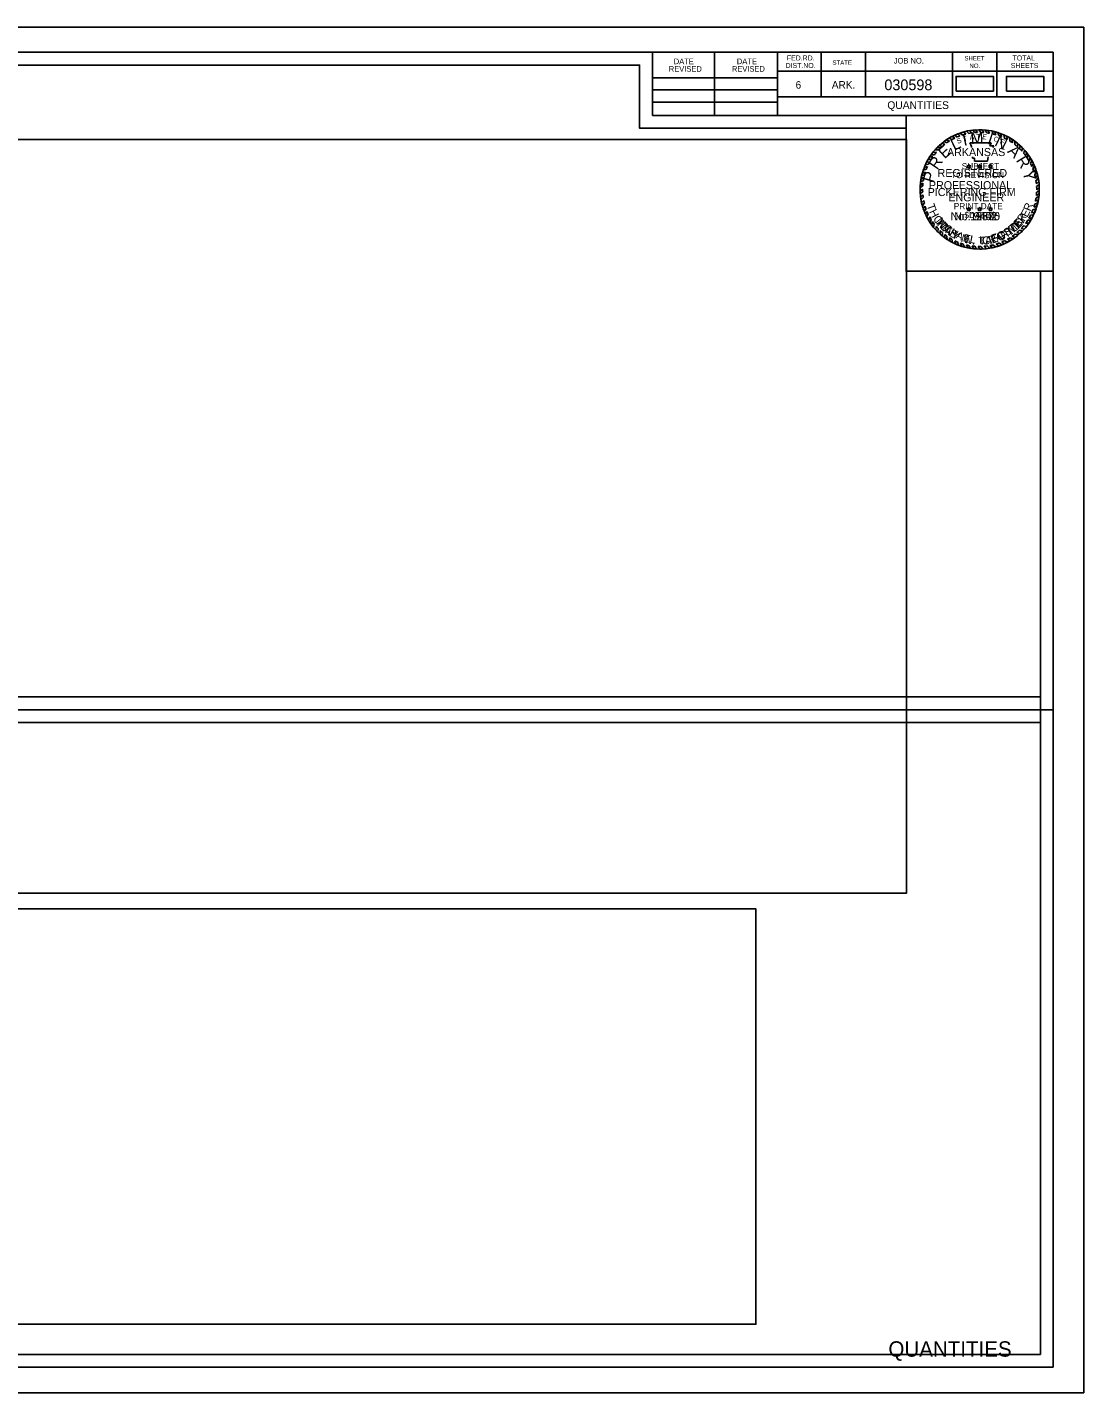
# Model space of a CAD drawing. Extents: x 1369904 to 1372237, y 380119 to 380332.
# Drawn here: x 1370071.9 to 1370236.9, y 380119.1 to 380332.4 of the extents above; entities that cross this region are included whole.
import ezdxf

# ---------------------------------------------------------------- set-up
doc = ezdxf.new("R2010")
doc.units = 0
for name, color, linetype in [('Default', 7, 'Continuous'), ('R_Border', 7, 'Continuous'), ('R_Border Notes', 7, 'Continuous'), ('R_Border Plan-Plan', 7, 'Continuous'), ('R_Border Title', 7, 'Continuous'), ('R_No Plot', 7, 'Continuous'), ('STAMP_PE_CRAFTON', 7, 'Continuous'), ('STAMP_PE_FOSTER', 7, 'Continuous'), ('STAMP_PE_SEAL-INFO', 7, 'Continuous'), ('STAMP_PE_TAEGTMEYER', 7, 'Continuous'), ('STAMP_PE_TXT', 7, 'Continuous'), ('STAMP_PRELIMINARY', 7, 'Continuous')]:
    doc.layers.add(name, color=color, linetype=linetype)

msp = doc.modelspace()

# ---------------------------------------------------------------- linework, layer by layer
at = {"layer": 'Default'}
for points in [[(1370217, 380322.41), (1370222.83, 380322.41), (1370222.83, 380324.72), (1370217, 380324.72)], [(1370224.87, 380322.41), (1370230.7, 380322.41), (1370230.7, 380324.72), (1370224.87, 380324.72)], [(1369918.18, 380197.09), (1370209.24, 380197.09), (1370209.24, 380314.85), (1369918.18, 380314.85)], [(1369962.47, 380129.75), (1370185.72, 380129.75), (1370185.72, 380194.65), (1369962.47, 380194.65)]]:
    msp.add_lwpolyline(points, close=True, dxfattribs=at)
at = {"layer": 'R_Border'}
for p, q in [((1369916, 380328.5), (1370232.18, 380328.5)), ((1370169.54, 380318.62), (1370169.54, 380328.5)), ((1370179.22, 380318.62), (1370179.22, 380328.5)), ((1370189.08, 380328.5), (1370189.08, 380318.62)), ((1370195.92, 380328.5), (1370195.92, 380321.56)), ((1370202.86, 380328.5), (1370202.86, 380321.56)), ((1370216.44, 380328.5), (1370216.44, 380321.56)), ((1370223.38, 380328.5), (1370223.38, 380321.56)), ((1370232.18, 380123.04), (1370232.18, 380328.5)), ((1370232.18, 380325.56), (1370189.08, 380325.56)), ((1370232.18, 380325.58), (1370232.18, 380325.58)), ((1370169.54, 380324.48), (1370189.08, 380324.48)), ((1370169.54, 380322.62), (1370189.08, 380322.62)), ((1370232.18, 380321.56), (1370189.08, 380321.56)), ((1370192.04, 380321.56), (1370232.18, 380321.56)), ((1370169.54, 380320.68), (1370189.08, 380320.68)), ((1370232.18, 380318.62), (1370169.54, 380318.62)), ((1370232.18, 380123.04), (1369916, 380123.04))]:
    msp.add_line(p, q, dxfattribs=at)
at = {"layer": 'R_Border Plan-Plan'}
msp.add_line((1369916, 380225.77), (1370232.18, 380225.77), dxfattribs=at)
at = {"layer": 'R_No Plot'}
for points in [[(1369903.6, 380332.4), (1370236.94, 380332.4), (1370236.94, 380119.06), (1369903.6, 380119.06)], [(1370230.18, 380227.77), (1369918, 380227.77), (1369918, 380326.5), (1370167.54, 380326.5), (1370167.54, 380316.62), (1370185.08, 380316.62), (1370209.18, 380316.62), (1370209.18, 380294.29), (1370230.18, 380294.29)], [(1369918, 380326.5), (1370167.54, 380326.5), (1370167.54, 380316.62), (1370185.08, 380316.62), (1370209.18, 380316.62), (1370209.18, 380294.29), (1370230.18, 380294.29), (1370230.18, 380125.04), (1369918, 380125.04)], [(1370209.18, 380318.62), (1370232.18, 380318.62), (1370232.18, 380294.29), (1370209.18, 380294.29)], [(1369918, 380223.77), (1370230.18, 380223.77), (1370230.18, 380125.04), (1369918, 380125.04)]]:
    msp.add_lwpolyline(points, close=True, dxfattribs=at)
at = {"layer": 'STAMP_PE_SEAL-INFO'}
for p, q in [((1370215.52, 380314.83), (1370215.96, 380314.63)), ((1370215.91, 380315.07), (1370216.34, 380314.85)), ((1370216.36, 380315.33), (1370216.82, 380315.1)), ((1370216.79, 380315.54), (1370217.18, 380315.26)), ((1370217.29, 380315.75), (1370217.59, 380315.43)), ((1370217.64, 380315.88), (1370218.02, 380315.57)), ((1370218.23, 380316.06), (1370218.52, 380315.71)), ((1370218.62, 380316.16), (1370218.98, 380315.82)), ((1370219.1, 380316.26), (1370219.4, 380315.89)), ((1370219.62, 380316.33), (1370219.9, 380315.95)), ((1370220.35, 380315.97), (1370220.04, 380316.37)), ((1370220.85, 380315.98), (1370220.57, 380316.39)), ((1370221.31, 380315.96), (1370221.05, 380316.38)), ((1370221.82, 380315.91), (1370221.52, 380316.35)), ((1370222.24, 380315.84), (1370221.98, 380316.3)), ((1370222.8, 380315.72), (1370222.63, 380316.18)), ((1370223.21, 380315.62), (1370223.05, 380316.09)), ((1370223.66, 380315.47), (1370223.52, 380315.95)), ((1370224.08, 380315.31), (1370223.93, 380315.81)), ((1370224.54, 380315.1), (1370224.43, 380315.6)), ((1370224.98, 380314.87), (1370224.9, 380315.38)), ((1370225.37, 380314.65), (1370225.33, 380315.15)), ((1370225.81, 380314.36), (1370225.77, 380314.88)), ((1370213.38, 380312.86), (1370213.93, 380312.88)), ((1370213.72, 380313.27), (1370214.24, 380313.23)), ((1370214.04, 380313.61), (1370214.59, 380313.57)), ((1370214.38, 380313.94), (1370214.84, 380313.8)), ((1370214.72, 380314.24), (1370215.25, 380314.14)), ((1370215.1, 380314.56), (1370215.56, 380314.36)), ((1370219.16, 380314.36), (1370222.5, 380314.36)), ((1370219.28, 380314.05), (1370219.16, 380314.36)), ((1370219.38, 380313.75), (1370219.28, 380314.05)), ((1370219.39, 380313.64), (1370219.38, 380313.75)), ((1370222.5, 380314.36), (1370222.28, 380313.87)), ((1370222.28, 380313.87), (1370222.91, 380313.87)), ((1370222.91, 380313.87), (1370222.76, 380313.64)), ((1370226.17, 380314.1), (1370226.2, 380314.58)), ((1370226.61, 380313.72), (1370226.63, 380314.25)), ((1370226.92, 380313.43), (1370226.99, 380313.93)), ((1370227.28, 380313.06), (1370227.35, 380313.58)), ((1370227.56, 380312.74), (1370227.69, 380313.21)), ((1370227.88, 380312.32), (1370228.02, 380312.82)), ((1370212.01, 380310.5), (1370212.52, 380310.64)), ((1370212.2, 380310.93), (1370212.7, 380311.03)), ((1370212.39, 380311.32), (1370212.88, 380311.38)), ((1370212.62, 380311.74), (1370213.11, 380311.76)), ((1370212.86, 380312.14), (1370213.38, 380312.18)), ((1370213.1, 380312.49), (1370213.6, 380312.48)), ((1370219.58, 380311.93), (1370219.55, 380312.15)), ((1370219.89, 380311.93), (1370219.58, 380311.93)), ((1370219.89, 380311.5), (1370219.89, 380311.93)), ((1370221.92, 380311.5), (1370219.89, 380311.5)), ((1370221.94, 380311.84), (1370221.92, 380311.5)), ((1370222.02, 380312.15), (1370221.94, 380311.84)), ((1370228.1, 380312.01), (1370228.28, 380312.47)), ((1370228.41, 380311.51), (1370228.59, 380312)), ((1370228.61, 380311.14), (1370228.84, 380311.59)), ((1370228.84, 380310.66), (1370229.07, 380311.15)), ((1370228.98, 380310.32), (1370229.24, 380310.76)), ((1370211.88, 380308.48), (1370211.44, 380308.25)), ((1370211.97, 380308.94), (1370211.5, 380308.69)), ((1370211.6, 380309.18), (1370212.07, 380309.37)), ((1370211.71, 380309.59), (1370212.19, 380309.76)), ((1370211.86, 380310.09), (1370212.35, 380310.23)), ((1370229.18, 380309.77), (1370229.45, 380310.25)), ((1370229.28, 380309.41), (1370229.58, 380309.86)), ((1370229.42, 380308.85), (1370229.73, 380309.3)), ((1370229.49, 380308.47), (1370229.84, 380308.82)), ((1370211.79, 380307.62), (1370211.36, 380307.36)), ((1370211.77, 380307.12), (1370211.36, 380306.79)), ((1370211.78, 380306.72), (1370211.38, 380306.39)), ((1370211.82, 380308.04), (1370211.39, 380307.76)), ((1370229.55, 380307.96), (1370229.92, 380308.3)), ((1370229.55, 380306.11), (1370229.98, 380306.37)), ((1370229.58, 380307.54), (1370229.97, 380307.84)), ((1370229.59, 380306.62), (1370230, 380306.9)), ((1370229.6, 380307.03), (1370230, 380307.35)), ((1370211.81, 380306.22), (1370211.44, 380305.86)), ((1370211.86, 380305.79), (1370211.51, 380305.42)), ((1370211.94, 380305.33), (1370211.6, 380304.96)), ((1370212.03, 380304.91), (1370211.72, 380304.5)), ((1370212.16, 380304.47), (1370211.86, 380304.05)), ((1370229.15, 380304.28), (1370229.64, 380304.48)), ((1370229.3, 380304.77), (1370229.77, 380304.98)), ((1370229.4, 380305.23), (1370229.86, 380305.42)), ((1370229.49, 380305.73), (1370229.94, 380305.95)), ((1370212.3, 380304.04), (1370212.02, 380303.63)), ((1370212.46, 380303.62), (1370212.2, 380303.19)), ((1370212.64, 380303.23), (1370212.41, 380302.77)), ((1370212.87, 380302.77), (1370212.68, 380302.28)), ((1370213.11, 380302.37), (1370212.92, 380301.9)), ((1370213.31, 380302.06), (1370213.2, 380301.51)), ((1370228.2, 380302.27), (1370228.67, 380302.26)), ((1370228.37, 380302.55), (1370228.87, 380302.61)), ((1370228.64, 380303.05), (1370229.13, 380303.12)), ((1370228.8, 380303.39), (1370229.29, 380303.48)), ((1370229.01, 380303.9), (1370229.5, 380304.03)), ((1370213.59, 380301.67), (1370213.49, 380301.14)), ((1370213.89, 380301.29), (1370213.81, 380300.77)), ((1370214.2, 380300.95), (1370214.13, 380300.43)), ((1370214.52, 380300.63), (1370214.49, 380300.1)), ((1370214.86, 380300.32), (1370214.86, 380299.79)), ((1370215.22, 380300.02), (1370215.24, 380299.5)), ((1370226.23, 380300.09), (1370226.7, 380299.95)), ((1370226.5, 380300.32), (1370226.98, 380300.19)), ((1370226.91, 380300.69), (1370227.35, 380300.55)), ((1370227.16, 380300.95), (1370227.64, 380300.86)), ((1370227.55, 380301.38), (1370228.01, 380301.3)), ((1370227.86, 380301.78), (1370228.36, 380301.78)), ((1370215.56, 380299.77), (1370215.6, 380299.25)), ((1370215.99, 380299.49), (1370216.05, 380298.98)), ((1370216.34, 380299.28), (1370216.43, 380298.77)), ((1370216.82, 380299.03), (1370216.98, 380298.51)), ((1370217.19, 380298.87), (1370217.37, 380298.35)), ((1370217.69, 380298.67), (1370217.89, 380298.17)), ((1370218.09, 380298.54), (1370218.32, 380298.05)), ((1370218.6, 380298.4), (1370218.82, 380297.93)), ((1370219, 380298.31), (1370219.25, 380297.86)), ((1370219.5, 380298.23), (1370219.74, 380297.79)), ((1370219.94, 380298.19), (1370220.21, 380297.76)), ((1370220.42, 380298.16), (1370220.72, 380297.74)), ((1370220.88, 380298.16), (1370221.23, 380297.76)), ((1370221.4, 380298.18), (1370221.73, 380297.8)), ((1370221.84, 380298.23), (1370222.21, 380297.87)), ((1370222.28, 380298.3), (1370222.67, 380297.96)), ((1370222.78, 380298.4), (1370223.15, 380298.08)), ((1370223.24, 380298.53), (1370223.65, 380298.23)), ((1370223.73, 380298.69), (1370224.17, 380298.42)), ((1370224.15, 380298.85), (1370224.57, 380298.59)), ((1370224.61, 380299.06), (1370225.09, 380298.85)), ((1370225.01, 380299.28), (1370225.43, 380299.04)), ((1370225.43, 380299.52), (1370225.88, 380299.33)), ((1370225.77, 380299.75), (1370226.21, 380299.56))]:
    msp.add_line(p, q, dxfattribs=at)
for radius, start, end in [(9.32, 123.6199, 126.5906), (9.32, 117.6544, 120.8099), (8.91, 115.6869, 119.1583), (9.32, 111.3124, 114.7026), (8.91, 110.3086, 113.1659), (9.32, 105.2339, 109.0352), (8.91, 104.0352, 107.3615), (9.32, 99.7525, 102.7765), (8.91, 98.258, 101.0329), (9.32, 93.9381, 96.5517), (8.91, 92.1102, 95.0367), (9.32, 87.7298, 90.6707), (8.91, 85.9628, 88.9097), (9.32, 81.9732, 84.8236), (8.91, 79.9264, 82.696), (9.32, 75.3125, 77.9426), (8.91, 73.5575, 76.2314), (9.32, 69.6061, 72.3058), (8.91, 67.6248, 70.504), (9.32, 63.1329, 66.2704), (8.91, 61.1558, 64.3784), (9.32, 56.9003, 60.0942), (9.32, 141.6056, 144.4486), (8.91, 139.301, 142.5873), (9.32, 135.4021, 138.3031), (8.91, 133.1331, 136.2562), (9.32, 129.7326, 132.5376), (8.91, 127.5297, 130.9683), (8.91, 121.9746, 125.11), (8.91, 54.9238, 58.2702), (8.91, 48.3016, 52.0395), (9.32, 50.3492, 53.7159), (8.91, 42.2212, 45.5512), (9.32, 44.3405, 47.3929), (8.91, 36.135, 39.5311), (9.32, 38.1247, 41.2316), (9.32, 152.864, 155.5189), (8.91, 156.3402, 159.2319), (9.32, 147.0072, 149.899), (8.91, 151.0315, 153.573), (8.91, 145.0197, 148.2104), (8.91, 29.9032, 33.6645), (9.32, 31.9614, 35.4294), (8.91, 23.7732, 27.2211), (9.32, 25.9391, 29.0125), (9.32, 19.9538, 23.3141), (9.32, 170.0003, 172.6878), (9.32, 164.3068, 166.894), (9.32, 158.4077, 161.0701), (8.91, 167.9048, 170.9039), (8.91, 162.4331, 165.0013), (8.91, 17.6802, 21.4251), (8.91, 11.5444, 15.2364), (8.91, 5.7599, 9.0606), (9.32, 13.8421, 17.4447), (9.32, 7.5852, 10.8621), (9.32, 175.7409, 178.2066), (9.32, 181.7251, 184.1626), (8.91, 179.6454, 182.2633), (8.91, 173.73, 176.4734), (8.91, 353.8632, 357.1274), (8.91, 359.7329, 3.0639), (9.32, 1.7215, 4.7268), (9.32, 355.7156, 358.9569), (9.32, 187.4204, 190.1927), (9.32, 193.0369, 195.9973), (8.91, 185.4539, 188.234), (8.91, 191.2274, 193.9858), (8.91, 196.9675, 199.8353), (8.91, 341.777, 345.0925), (8.91, 348.0778, 351.3435), (9.32, 343.8925, 347.035), (9.32, 349.8305, 353.0885), (9.32, 198.8967, 201.6281), (9.32, 204.5479, 207.4328), (8.91, 202.7761, 205.4791), (9.32, 210.8636, 213.6571), (8.91, 208.7883, 211.7934), (8.91, 214.1838, 217.2747), (8.91, 323.5851, 327.4407), (9.32, 325.4405, 328.9872), (8.91, 329.5549, 333.2076), (8.91, 335.6038, 339.1858), (9.32, 331.4037, 334.9332), (9.32, 337.3837, 340.9933), (9.32, 216.6115, 219.491), (9.32, 222.48, 225.3801), (8.91, 220.3909, 223.3056), (9.32, 228.3665, 231.348), (8.91, 226.2494, 229.2407), (8.91, 232.229, 234.9336), (8.91, 304.823, 308.5143), (9.32, 306.3721, 310.208), (8.91, 310.7744, 314.3161), (9.32, 312.4518, 315.6633), (8.91, 316.6531, 320.3711), (9.32, 318.2846, 321.8043), (9.32, 234.295, 236.9452), (8.91, 238.2223, 240.8353), (9.32, 240.1977, 242.8613), (8.91, 244.3204, 246.9486), (9.32, 246.576, 249.1558), (8.91, 250.3491, 253.1216), (9.32, 252.5967, 255.3252), (8.91, 256.505, 259.1192), (9.32, 258.4433, 261.1398), (8.91, 262.3783, 265.2012), (9.32, 264.1978, 267.1009), (8.91, 268.3215, 271.277), (9.32, 270.2548, 273.3361), (8.91, 274.6157, 277.4486), (9.32, 276.4239, 279.4357), (8.91, 280.3459, 283.5814), (9.32, 282.3199, 285.3702), (8.91, 286.6423, 289.9783), (9.32, 288.5709, 291.9733), (8.91, 292.8745, 296.1185), (9.32, 294.6481, 298.2166), (8.91, 299.0768, 302.1724), (9.32, 300.621, 303.8703)]:
    msp.add_arc((1370220.68, 380307.07), radius, start, end, dxfattribs=at)
at = {"layer": 'STAMP_PE_TXT'}
for p, q in [((1370218.86, 380310.64), (1370218.66, 380310.78)), ((1370218.66, 380310.78), (1370218.91, 380310.78)), ((1370218.79, 380310.41), (1370218.86, 380310.64)), ((1370218.98, 380310.55), (1370218.79, 380310.41)), ((1370218.91, 380310.78), (1370218.98, 380311.02)), ((1370218.98, 380311.02), (1370219.06, 380310.78)), ((1370219.18, 380310.41), (1370218.98, 380310.55)), ((1370219.06, 380310.78), (1370219.31, 380310.78)), ((1370219.31, 380310.78), (1370219.11, 380310.64)), ((1370219.11, 380310.64), (1370219.18, 380310.41)), ((1370220.56, 380310.64), (1370220.36, 380310.78)), ((1370220.36, 380310.78), (1370220.61, 380310.78)), ((1370220.48, 380310.41), (1370220.56, 380310.64)), ((1370220.68, 380310.55), (1370220.48, 380310.41)), ((1370220.61, 380310.78), (1370220.68, 380311.02)), ((1370220.68, 380311.02), (1370220.76, 380310.78)), ((1370220.88, 380310.41), (1370220.68, 380310.55)), ((1370220.76, 380310.78), (1370221, 380310.78)), ((1370221, 380310.78), (1370220.81, 380310.64)), ((1370220.81, 380310.64), (1370220.88, 380310.41)), ((1370222.26, 380310.64), (1370222.06, 380310.78)), ((1370222.06, 380310.78), (1370222.31, 380310.78)), ((1370222.18, 380310.41), (1370222.26, 380310.64)), ((1370222.38, 380310.55), (1370222.18, 380310.41)), ((1370222.31, 380310.78), (1370222.38, 380311.02)), ((1370222.38, 380311.02), (1370222.46, 380310.78)), ((1370222.58, 380310.41), (1370222.38, 380310.55)), ((1370222.46, 380310.78), (1370222.7, 380310.78)), ((1370222.7, 380310.78), (1370222.5, 380310.64)), ((1370222.5, 380310.64), (1370222.58, 380310.41)), ((1370218.91, 380304.08), (1370218.98, 380304.31)), ((1370218.98, 380304.31), (1370219.06, 380304.08)), ((1370220.61, 380304.08), (1370220.68, 380304.31)), ((1370220.68, 380304.31), (1370220.76, 380304.08)), ((1370222.31, 380304.08), (1370222.38, 380304.31)), ((1370222.38, 380304.31), (1370222.46, 380304.08)), ((1370218.86, 380303.93), (1370218.66, 380304.08)), ((1370218.66, 380304.08), (1370218.91, 380304.08)), ((1370218.79, 380303.7), (1370218.86, 380303.93)), ((1370218.98, 380303.84), (1370218.79, 380303.7)), ((1370219.18, 380303.7), (1370218.98, 380303.84)), ((1370219.06, 380304.08), (1370219.31, 380304.08)), ((1370219.31, 380304.08), (1370219.11, 380303.93)), ((1370219.11, 380303.93), (1370219.18, 380303.7)), ((1370220.56, 380303.93), (1370220.36, 380304.08)), ((1370220.36, 380304.08), (1370220.61, 380304.08)), ((1370220.48, 380303.7), (1370220.56, 380303.93)), ((1370220.68, 380303.84), (1370220.48, 380303.7)), ((1370220.88, 380303.7), (1370220.68, 380303.84)), ((1370220.76, 380304.08), (1370221, 380304.08)), ((1370221, 380304.08), (1370220.81, 380303.93)), ((1370220.81, 380303.93), (1370220.88, 380303.7)), ((1370222.26, 380303.93), (1370222.06, 380304.08)), ((1370222.06, 380304.08), (1370222.31, 380304.08)), ((1370222.18, 380303.7), (1370222.26, 380303.93)), ((1370222.38, 380303.84), (1370222.18, 380303.7)), ((1370222.58, 380303.7), (1370222.38, 380303.84)), ((1370222.46, 380304.08), (1370222.7, 380304.08)), ((1370222.7, 380304.08), (1370222.5, 380303.93)), ((1370222.5, 380303.93), (1370222.58, 380303.7))]:
    msp.add_line(p, q, dxfattribs=at)
at = {"layer": 'STAMP_PRELIMINARY'}
msp.add_circle((1370220.68, 380307.07), 9.32, dxfattribs=at)

# ---------------------------------------------------------------- texts
at = {"layer": 'R_Border'}
for s, height, p in [('FED.RD.', 0.782, (1370190.56, 380327.22)), ('JOB NO.', 0.879, (1370207.26, 380326.74)), ('SHEET', 0.684, (1370218.3, 380327.22)), ('TOTAL', 0.782, (1370225.82, 380327.22)), ('REVISED', 0.879, (1370172.1, 380325.46)), ('DATE', 0.879, (1370172.88, 380326.64)), ('REVISED', 0.879, (1370181.96, 380325.46)), ('DATE', 0.879, (1370182.74, 380326.64)), ('DIST.NO.', 0.782, (1370190.36, 380326.04)), ('STATE', 0.684, (1370197.68, 380326.54)), ('NO.', 0.684, (1370219.08, 380326.04)), ('SHEETS', 0.782, (1370225.54, 380326.04)), ('6', 1.17, (1370191.92, 380322.82)), ('ARK.', 1.172, (1370197.58, 380322.82))]:
    msp.add_text(s, height=height, dxfattribs=at).set_placement(p)
at = {"layer": 'R_Border Notes'}
for s, height, p in [('030598', 1.68, (1370205.79, 380322.57)), ('QUANTITIES', 1.2, (1370206.25, 380319.64))]:
    msp.add_text(s, height=height, dxfattribs=at).set_placement(p)
at = {"layer": 'R_Border Title'}
msp.add_text('QUANTITIES', height=2.4, dxfattribs=at).set_placement((1370206.42, 380124.69))
at = {"layer": 'STAMP_PE_CRAFTON'}
for s, rotation, p in [('T', 310.7442, (1370213.65, 380301.97)), ('N', 49.2411, (1370226.97, 380301.09)), ('O', 317.6422, (1370214.32, 380301.15)), ('N', 324.4537, (1370215.16, 380300.37)), ('Y', 331.1686, (1370216.19, 380299.65)), ('N', 347.4752, (1370218.25, 380298.74)), ('R', 14.8189, (1370222.25, 380298.52)), ('A', 20.5125, (1370223.36, 380298.82)), ('F', 28.7821, (1370224.34, 380299.2)), ('T', 34.1136, (1370225.26, 380299.71)), ('O', 41.8391, (1370226.12, 380300.31)), ('.', 356.8926, (1370219.48, 380298.46)), ('C', 6.0117, (1370221.15, 380298.41))]:
    msp.add_text(s, height=1.25, rotation=rotation, dxfattribs=at).set_placement(p)
msp.add_text('No. 12370', height=1.25, dxfattribs=at).set_placement((1370216.14, 380302.26))
at = {"layer": 'STAMP_PE_FOSTER'}
for s, rotation, p in [('M', 308.339, (1370213.8, 380302.09)), ('E', 46.9613, (1370226.68, 380301.06)), ('R', 54.5031, (1370227.41, 380301.88)), ('I', 314.1842, (1370214.6, 380301.15)), ('C', 319.8733, (1370214.95, 380300.8)), ('H', 327.7235, (1370215.88, 380300.06)), ('A', 335.7276, (1370216.86, 380299.48)), ('E', 343.5779, (1370218, 380299.01)), ('L', 350.8115, (1370219.06, 380298.73)), ('F', 15.8691, (1370222.72, 380298.82)), ('O', 23.719, (1370223.76, 380299.15)), ('S', 31.7234, (1370224.87, 380299.68)), ('T', 39.4194, (1370225.83, 380300.31)), ('L', 1.2666, (1370220.6, 380298.58)), ('.', 6.8035, (1370221.64, 380298.63))]:
    msp.add_text(s, height=1.2, rotation=rotation, dxfattribs=at).set_placement(p)
msp.add_text('No. 9402', height=1.25, dxfattribs=at).set_placement((1370216.67, 380302.26))
at = {"layer": 'STAMP_PE_TAEGTMEYER'}
for s, rotation, p in [('T', 289.646, (1370212.38, 380304.58)), ('R', 69.57, (1370228.63, 380303.58)), ('H', 296.7339, (1370212.74, 380303.59)), ('O', 303.7708, (1370213.33, 380302.49)), ('M', 314.2033, (1370213.98, 380301.53)), ('E', 46.8094, (1370226.72, 380300.84)), ('Y', 53.9986, (1370227.46, 380301.66)), ('E', 63.0984, (1370228.13, 380302.6)), ('A', 321.0594, (1370214.95, 380300.57)), ('S', 327.8239, (1370215.77, 380299.93)), ('N', 344.2727, (1370217.67, 380298.92)), ('E', 17.6836, (1370222.63, 380298.6)), ('G', 23.3052, (1370223.68, 380298.93)), ('T', 31.466, (1370224.78, 380299.42)), ('M', 39.3, (1370225.68, 380299.97)), ('.', 350.6464, (1370218.88, 380298.59)), ('T', 3.0061, (1370220.55, 380298.39)), ('A', 8.9826, (1370221.59, 380298.44))]:
    msp.add_text(s, height=1.25, rotation=rotation, dxfattribs=at).set_placement(p)
msp.add_text('No. 19605', height=1.25, dxfattribs=at).set_placement((1370216.14, 380302.26))
at = {"layer": 'STAMP_PE_TXT'}
for s, rotation, p in [('S', 23.5541, (1370217.28, 380314.17)), ('T', 16.311, (1370218.2, 380314.54)), ('A', 9.0679, (1370219.17, 380314.8)), ('T', 1.8248, (1370220.15, 380314.93)), ('E', 355.2002, (1370221.06, 380314.93)), ('O', 342.2506, (1370222.79, 380314.66)), ('F', 335.0075, (1370223.76, 380314.32))]:
    msp.add_text(s, height=0.781, rotation=rotation, dxfattribs=at).set_placement(p)
for s, p in [('ARKANSAS', (1370215.58, 380312.28)), ('REGISTERED', (1370214.1, 380309.01)), ('PROFESSIONAL', (1370212.75, 380307.11)), ('ENGINEER', (1370215.79, 380305.21))]:
    msp.add_text(s, height=1.25, dxfattribs=at).set_placement(p)
at = {"layer": 'STAMP_PRELIMINARY'}
for s, rotation, p in [('L', 25.513, (1370216.69, 380313.09)), ('I', 12.5248, (1370218.22, 380313.85)), ('M', 3.1074, (1370219.32, 380314.16)), ('I', 342.3164, (1370221.79, 380314.23)), ('N', 333.9382, (1370222.89, 380313.96)), ('E', 42.3578, (1370215.21, 380311.76)), ('A', 315.6579, (1370224.93, 380312.93)), ('R', 56.2292, (1370214.05, 380310.03)), ('R', 301.3831, (1370226.3, 380311.62)), ('P', 73.913, (1370213.5, 380308.01)), ('Y', 283.2593, (1370227.38, 380309.83))]:
    msp.add_text(s, height=1.8, rotation=rotation, dxfattribs=at).set_placement(p)
for s, height, p in [('SUBJECT', 0.96, (1370217.88, 380310.22)), ('TO REVISION', 0.96, (1370216.22, 380308.83)), ('PICKERING FIRM', 1.25, (1370212.56, 380306.03)), ('PRINT DATE', 0.96, (1370216.64, 380303.98)), ('$DATE$', 0.96, (1370218.32, 380302.6))]:
    msp.add_text(s, height=height, dxfattribs=at).set_placement(p)

doc.saveas('drawing.dxf')
